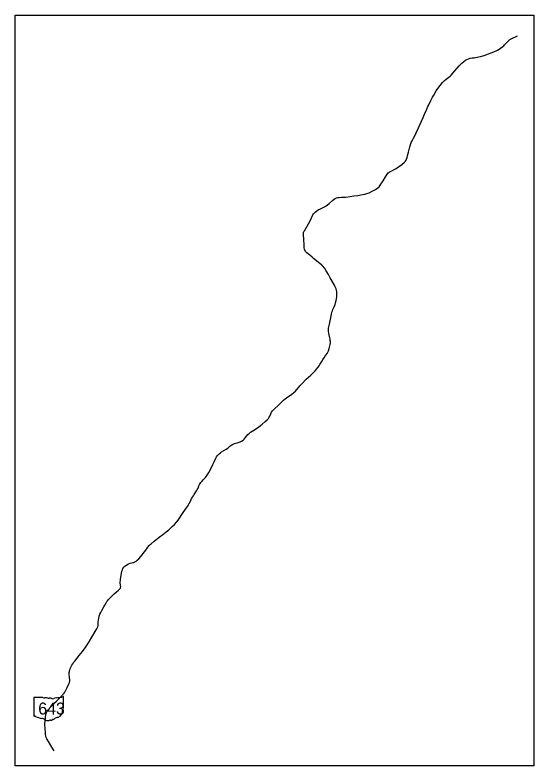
# Model space of a CAD drawing. Extents: x -6.3 to 34, y 0 to 22.
# Drawn here: x -6.32 to -2.39, y 15.28 to 20.96 of the extents above; entities that cross this region are included whole.
import ezdxf

# ---------------------------------------------------------------- set-up
doc = ezdxf.new("R2010")
doc.units = 0
for name, color, linetype in [('GM_X_State_Route', 7, 'Continuous'), ('GM_X_State_Shield', 7, 'Continuous'), ('SH_Text', 7, 'Continuous')]:
    doc.layers.add(name, color=color, linetype=linetype)

msp = doc.modelspace()

# ---------------------------------------------------------------- linework, layer by layer
at = {"layer": 'GM_X_State_Route'}
for points in [[(-2.6153, 20.7265), (-2.6086, 20.7331), (-2.5922, 20.7513), (-2.5849, 20.7594), (-2.5771, 20.7664), (-2.5677, 20.7733), (-2.553, 20.7808), (-2.511, 20.8007)], [(-4.0422, 19.4681), (-4.0327, 19.4755), (-4.0192, 19.4836), (-4.0029, 19.4925), (-3.9833, 19.5019), (-3.9732, 19.5068), (-3.9653, 19.5112), (-3.9531, 19.5194), (-3.937, 19.5321), (-3.9078, 19.5582), (-3.8987, 19.565), (-3.8901, 19.5705), (-3.8808, 19.5748), (-3.8717, 19.5775), (-3.8602, 19.5792), (-3.8421, 19.5796), (-3.8138, 19.5803), (-3.7944, 19.582), (-3.7779, 19.5844), (-3.749, 19.5899), (-3.7208, 19.5942), (-3.6836, 19.6003), (-3.6664, 19.6034), (-3.6506, 19.6071), (-3.6344, 19.6133), (-3.6112, 19.6247), (-3.5867, 19.6378), (-3.5687, 19.6506), (-3.5582, 19.6598), (-3.5527, 19.6662), (-3.5446, 19.6781), (-3.5391, 19.6882), (-3.5284, 19.7053), (-3.509, 19.7343), (-3.4953, 19.7568), (-3.489, 19.7649), (-3.4835, 19.7694), (-3.4751, 19.7745), (-3.4626, 19.7805), (-3.4447, 19.7893), (-3.4297, 19.7984), (-3.3877, 19.8282), (-3.3658, 19.8459), (-3.3601, 19.8514), (-3.3543, 19.8602), (-3.35, 19.8691), (-3.3461, 19.8814), (-3.3405, 19.9027), (-3.3363, 19.921), (-3.3309, 19.9416), (-3.3251, 19.9616), (-3.3147, 19.9933), (-3.3086, 20.008), (-3.2979, 20.027), (-3.2857, 20.0492), (-3.2769, 20.0669), (-3.2604, 20.1048), (-3.2258, 20.183), (-3.2145, 20.2095), (-3.1985, 20.2455), (-3.1893, 20.2653), (-3.1818, 20.2798), (-3.1666, 20.3117), (-3.1541, 20.3362), (-3.1452, 20.3527), (-3.1259, 20.3856), (-3.1142, 20.4024), (-3.0959, 20.4264), (-3.0799, 20.4472), (-3.0723, 20.4563), (-3.0643, 20.4638), (-3.0521, 20.4734), (-3.0311, 20.4894), (-3.0217, 20.4972), (-3.0136, 20.5043), (-2.9852, 20.5371), (-2.953, 20.573), (-2.9328, 20.5938), (-2.9179, 20.607), (-2.9054, 20.6166), (-2.8942, 20.6229), (-2.8826, 20.6277), (-2.8684, 20.6317), (-2.8552, 20.6338), (-2.8391, 20.6352), (-2.828, 20.6365), (-2.8151, 20.6389), (-2.79, 20.6455), (-2.7626, 20.6536), (-2.7308, 20.6645), (-2.71, 20.6721), (-2.6912, 20.6802), (-2.6624, 20.6931), (-2.6499, 20.6995), (-2.6383, 20.7066), (-2.6225, 20.7194), (-2.6153, 20.7265)], [(-4.1206, 19.1786), (-4.1236, 19.1874), (-4.1252, 19.1981), (-4.1268, 19.2333), (-4.1275, 19.2474), (-4.1283, 19.2616), (-4.1306, 19.2943), (-4.1309, 19.3065), (-4.1299, 19.3135), (-4.1277, 19.3206), (-4.1247, 19.3268), (-4.1037, 19.3612), (-4.0903, 19.385), (-4.0788, 19.4077), (-4.0603, 19.4472), (-4.0554, 19.455), (-4.0486, 19.4621), (-4.0422, 19.4681)], [(-4.0655, 19.1264), (-4.0826, 19.1406), (-4.1059, 19.1601), (-4.113, 19.1671), (-4.1171, 19.1719), (-4.1206, 19.1786)], [(-4.0759, 18.2344), (-4.0581, 18.2517), (-4.0428, 18.2675), (-4.031, 18.2812), (-4.0226, 18.2921), (-4.0135, 18.3052), (-4.0067, 18.3153), (-3.9884, 18.3452), (-3.9845, 18.3512), (-3.9747, 18.3655), (-3.9633, 18.3821), (-3.9529, 18.398), (-3.947, 18.408), (-3.9425, 18.4173), (-3.9356, 18.4368), (-3.9309, 18.4545), (-3.9287, 18.4657), (-3.9274, 18.4784), (-3.9273, 18.4884), (-3.9282, 18.4963), (-3.9299, 18.5063), (-3.9322, 18.5161), (-3.9372, 18.5379), (-3.9398, 18.551), (-3.9415, 18.5663), (-3.9415, 18.5799), (-3.941, 18.5903), (-3.9393, 18.6005), (-3.935, 18.6194), (-3.926, 18.6582), (-3.9185, 18.6951), (-3.9156, 18.7093), (-3.9122, 18.7213), (-3.9087, 18.7311), (-3.905, 18.74), (-3.899, 18.752), (-3.8919, 18.7677), (-3.8879, 18.7805), (-3.8844, 18.7976), (-3.8816, 18.8123), (-3.8794, 18.8275), (-3.878, 18.8428), (-3.8781, 18.8525), (-3.8791, 18.8646), (-3.8816, 18.8762), (-3.885, 18.8872), (-3.8909, 18.9022), (-3.8967, 18.9145), (-3.9034, 18.927), (-3.928, 18.9697), (-3.9423, 18.9952), (-3.9593, 19.0239), (-3.9696, 19.0398), (-3.9734, 19.045), (-3.9812, 19.0548), (-3.9925, 19.0655), (-4.0201, 19.0892), (-4.0541, 19.1169), (-4.0655, 19.1264)], [(-4.8489, 17.4969), (-4.8308, 17.53), (-4.8175, 17.5573), (-4.8081, 17.5783), (-4.7946, 17.6067), (-4.7888, 17.6171), (-4.7844, 17.6239), (-4.7775, 17.6318), (-4.77, 17.6392), (-4.76, 17.6467), (-4.7507, 17.6532), (-4.7176, 17.6729), (-4.7036, 17.6822), (-4.6887, 17.6954), (-4.6825, 17.7009), (-4.6746, 17.7064), (-4.6636, 17.7121), (-4.6537, 17.716), (-4.6344, 17.7216), (-4.6106, 17.729), (-4.6004, 17.7332), (-4.5881, 17.7408), (-4.5791, 17.75), (-4.5628, 17.7718), (-4.552, 17.7852), (-4.5409, 17.7961), (-4.5335, 17.8025), (-4.5208, 17.8111), (-4.507, 17.818), (-4.4948, 17.8246), (-4.4836, 17.8317), (-4.4717, 17.8408), (-4.4559, 17.8534), (-4.4439, 17.8631), (-4.4204, 17.8826), (-4.4052, 17.8966), (-4.3966, 17.9069), (-4.3914, 17.9148), (-4.3866, 17.9246), (-4.3796, 17.9416), (-4.3745, 17.9528), (-4.3669, 17.9639), (-4.3594, 17.9724), (-4.3152, 18.0118), (-4.2967, 18.0307), (-4.2824, 18.0454), (-4.2708, 18.0551), (-4.2507, 18.0688), (-4.2209, 18.0881), (-4.2034, 18.1019), (-4.1922, 18.1122), (-4.1805, 18.1253), (-4.1642, 18.1462), (-4.1576, 18.1542), (-4.1423, 18.1706), (-4.1102, 18.2026), (-4.0759, 18.2344)], [(-5.4108, 16.819), (-5.407, 16.821), (-5.3984, 16.8263), (-5.39, 16.8332), (-5.3789, 16.8449), (-5.3638, 16.8629), (-5.3453, 16.8855), (-5.326, 16.9102), (-5.3093, 16.9326), (-5.2997, 16.9439), (-5.2913, 16.9527), (-5.2848, 16.9586), (-5.2616, 16.9773), (-5.2246, 17.0074), (-5.1964, 17.0294), (-5.1705, 17.0496), (-5.1509, 17.0647), (-5.138, 17.0757), (-5.1251, 17.0881), (-5.1089, 17.1051), (-5.0912, 17.125), (-5.0811, 17.1371), (-5.0698, 17.1525), (-5.0519, 17.1791), (-5.0184, 17.2272), (-5.0091, 17.2403), (-4.9963, 17.2621), (-4.9852, 17.2851), (-4.9779, 17.2995), (-4.9648, 17.3216), (-4.9576, 17.3321), (-4.9407, 17.3576), (-4.9353, 17.3679), (-4.9297, 17.379), (-4.9229, 17.3959), (-4.9183, 17.4058), (-4.9141, 17.4137), (-4.9094, 17.4205), (-4.902, 17.4299), (-4.8909, 17.441), (-4.8801, 17.4515), (-4.8724, 17.4599), (-4.8668, 17.467), (-4.8598, 17.4777), (-4.8489, 17.4969)], [(-5.4442, 16.8105), (-5.4328, 16.8135), (-5.4241, 16.8155), (-5.4162, 16.8172), (-5.4119, 16.8184), (-5.4108, 16.819)], [(-5.8002, 16.1496), (-5.7824, 16.1734), (-5.7729, 16.1869), (-5.7642, 16.2), (-5.7596, 16.2084), (-5.7266, 16.2647), (-5.7082, 16.2942), (-5.6957, 16.3137), (-5.6904, 16.3237), (-5.6881, 16.3305), (-5.6867, 16.3395), (-5.6862, 16.3532), (-5.6856, 16.3656), (-5.6843, 16.3802), (-5.6814, 16.3953), (-5.6769, 16.4108), (-5.6721, 16.4247), (-5.6666, 16.4387), (-5.6582, 16.4541), (-5.6432, 16.4807), (-5.6354, 16.4945), (-5.6258, 16.5112), (-5.6199, 16.5212), (-5.6155, 16.5269), (-5.6102, 16.5334), (-5.6, 16.5442), (-5.5868, 16.557), (-5.5749, 16.5682), (-5.5636, 16.5797), (-5.5504, 16.5919), (-5.5315, 16.6081), (-5.5221, 16.6162), (-5.5175, 16.6224), (-5.5159, 16.6267), (-5.5148, 16.6318), (-5.5184, 16.66), (-5.5164, 16.6912), (-5.5119, 16.719), (-5.5054, 16.752), (-5.5025, 16.7622), (-5.4979, 16.7717), (-5.491, 16.7804), (-5.4828, 16.7883), (-5.4795, 16.7907)], [(-5.4795, 16.7907), (-5.4684, 16.7987), (-5.455, 16.8059), (-5.4442, 16.8105)], [(-5.9305, 15.8493), (-5.9201, 15.8704), (-5.9077, 15.8981), (-5.9037, 15.9096), (-5.9014, 15.9205), (-5.9007, 15.9303), (-5.9016, 15.9434), (-5.9046, 15.9751), (-5.9044, 15.9831), (-5.9037, 15.9906), (-5.9021, 15.9984), (-5.8988, 16.0083), (-5.8946, 16.019), (-5.8901, 16.0289), (-5.8851, 16.0386), (-5.8787, 16.0495), (-5.8738, 16.0579), (-5.8631, 16.071), (-5.8287, 16.1129), (-5.8047, 16.1435), (-5.8002, 16.1496)], [(-6.073, 15.6909), (-6.0663, 15.6989), (-6.0436, 15.7241), (-6.0204, 15.7485), (-6.0011, 15.7678), (-5.9742, 15.7946), (-5.9497, 15.8192), (-5.9421, 15.8284), (-5.9377, 15.8354), (-5.9324, 15.8454), (-5.9305, 15.8493)], [(-6.0188, 15.3907), (-6.0359, 15.4197), (-6.0626, 15.4632), (-6.0734, 15.4816), (-6.0784, 15.4926), (-6.0826, 15.5042), (-6.0845, 15.5149), (-6.0856, 15.5269), (-6.0878, 15.5632), (-6.0892, 15.5884), (-6.0889, 15.601), (-6.0882, 15.6127), (-6.0845, 15.6465), (-6.0825, 15.6661), (-6.0806, 15.6739), (-6.0777, 15.6823), (-6.073, 15.6909)]]:
    msp.add_lwpolyline(points, dxfattribs=at)
at = {"layer": 'GM_X_State_Shield'}
for p, q in [((-6.1049, 15.7963), (-6.171, 15.7963)), ((-5.9474, 15.7279), (-5.9474, 15.7997)), ((-6.1733, 15.7939), (-6.1733, 15.6568)), ((-5.9474, 15.7279), (-5.9474, 15.7279))]:
    msp.add_line(p, q, dxfattribs=at)
for centre, major_axis, start_param, end_param in [((-6.1707, 15.7942), (0.00262, 0), 1.712693, 3.28349), ((-6.0891, 15.8122), (0.0254, 0), 4.042523, 4.731795), ((-6.0278, 15.9832), (0.2395, 0), 4.814394, 5.042369), ((-5.9499, 15.8), (0.00251, 0), 6.141152, 7.989035), ((-6.0807, 15.7193), (0.0911, 0), 1.404758, 1.657858), ((-6.06, 15.7949), (0.00732, 0), 3.836095, 5.185415), ((-6.0493, 15.7791), (0.0152, 0), 0.950623, 2.079405), ((-6.0296, 15.8008), (0.0183, 0), 4.081561, 5.145723), ((-5.9973, 15.7544), (0.0482, 0), 1.699011, 2.107814), ((-6.0144, 15.6888), (0.0599, 0), 5.101752, 6.440018), ((-5.9384, 15.6979), (0.017, 0), 2.387724, 3.262537), ((-5.948, 15.7227), (0.00389, 0), 1.883978, 3.671073), ((-5.9727, 15.7136), (0.0234, 0), 5.934695, 6.695948), ((-5.9501, 15.7276), (0.00269, 0), 5.05454, 6.418171), ((-6.1706, 15.6565), (0.00264, 0), 3.00124, 4.508301), ((-6.1702, 15.6705), (0.0201, 0), 4.665946, 4.897461), ((-6.1661, 15.6488), (0.00726, 0), 0.519207, 1.627899), ((-6.0744, 15.7721), (0.173, 0), 4.195997, 4.488961), ((-6.126, 15.5951), (0.0541, 0), 0.823519, 1.323587), ((-6.0674, 15.6482), (0.0343, 0), 4.026481, 4.996735), ((-6.0451, 15.6379), (0.0183, 0), 4.691044, 5.507374), ((-6.0285, 15.6246), (0.00515, 0), 1.147584, 2.315152), ((-6.0307, 15.6435), (0.0194, 0), 4.937069, 5.64225), ((-5.9892, 15.6183), (0.0328, 0), 1.647645, 2.488434), ((-6.0476, 15.6007), (0.0282, 0), 1.495662, 1.94098)]:
    msp.add_ellipse(centre, major_axis=major_axis, ratio=0.8, start_param=start_param, end_param=end_param, dxfattribs=at)
at = {"layer": 'SH_Text'}
msp.add_lwpolyline([(-6.3153, 20.9586), (-2.386, 20.9586), (-2.386, 15.2769), (-6.3153, 15.2769)], close=True, dxfattribs=at)

# ---------------------------------------------------------------- texts
at = {"layer": 'GM_X_State_Shield'}
msp.add_text('643', height=0.09035, dxfattribs=at).set_placement((-6.1394, 15.6664))

doc.saveas('drawing.dxf')
